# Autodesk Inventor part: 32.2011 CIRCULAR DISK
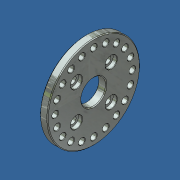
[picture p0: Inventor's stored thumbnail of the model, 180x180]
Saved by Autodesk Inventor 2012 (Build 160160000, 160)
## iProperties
Created: 2016-09
Part Number: 32.2011 CIRCULAR DISK
Material: Default
Document SubType Name: Modeling
Designer: Admin
Density: 1 g/cm^3
Author: Admin
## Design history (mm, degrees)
feature "Base1"
body "Solid1"
